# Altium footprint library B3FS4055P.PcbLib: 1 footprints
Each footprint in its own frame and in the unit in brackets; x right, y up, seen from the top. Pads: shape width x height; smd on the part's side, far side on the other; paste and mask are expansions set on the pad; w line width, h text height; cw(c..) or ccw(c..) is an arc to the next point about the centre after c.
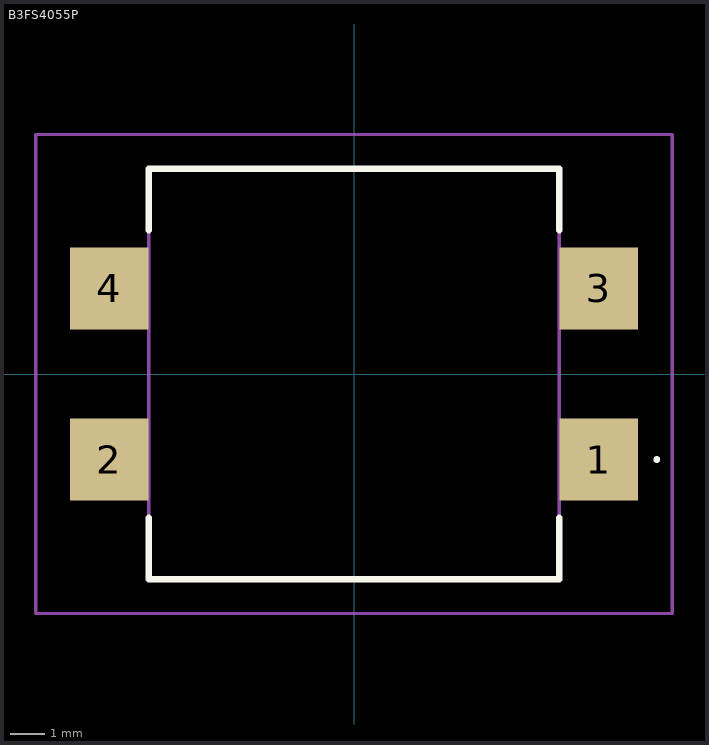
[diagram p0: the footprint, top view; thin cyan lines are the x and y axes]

## B3FS4055P [mm]
pads (4):
  rect 2.3x2.4 smd: 1(7.15,-2.5) 2(-7.15,-2.5) 3(7.15,2.5) 4(-7.15,2.5)
Top Overlay:
  lines w0.1: 8.8,-2.5 8.8,-2.5 ; 8.8,-2.5 ccw(c8.85,-2.5) 8.9,-2.5 ; 8.8,-2.5 cw(c8.85,-2.5) 8.9,-2.5 ; 8.9,-2.5 8.9,-2.5
  lines w0.2: -6,-4.2 -6,-6 6,-6 6,-4.2 ; -6,4.2 -6,6 6,6 6,4.2
Mechanical 15:
  lines w0.1: -6,-6 6,-6 6,6 -6,6 -6,-6
Mechanical 20:
  lines w0.1: -9.3,-7 9.3,-7 9.3,7 -9.3,7 -9.3,-7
